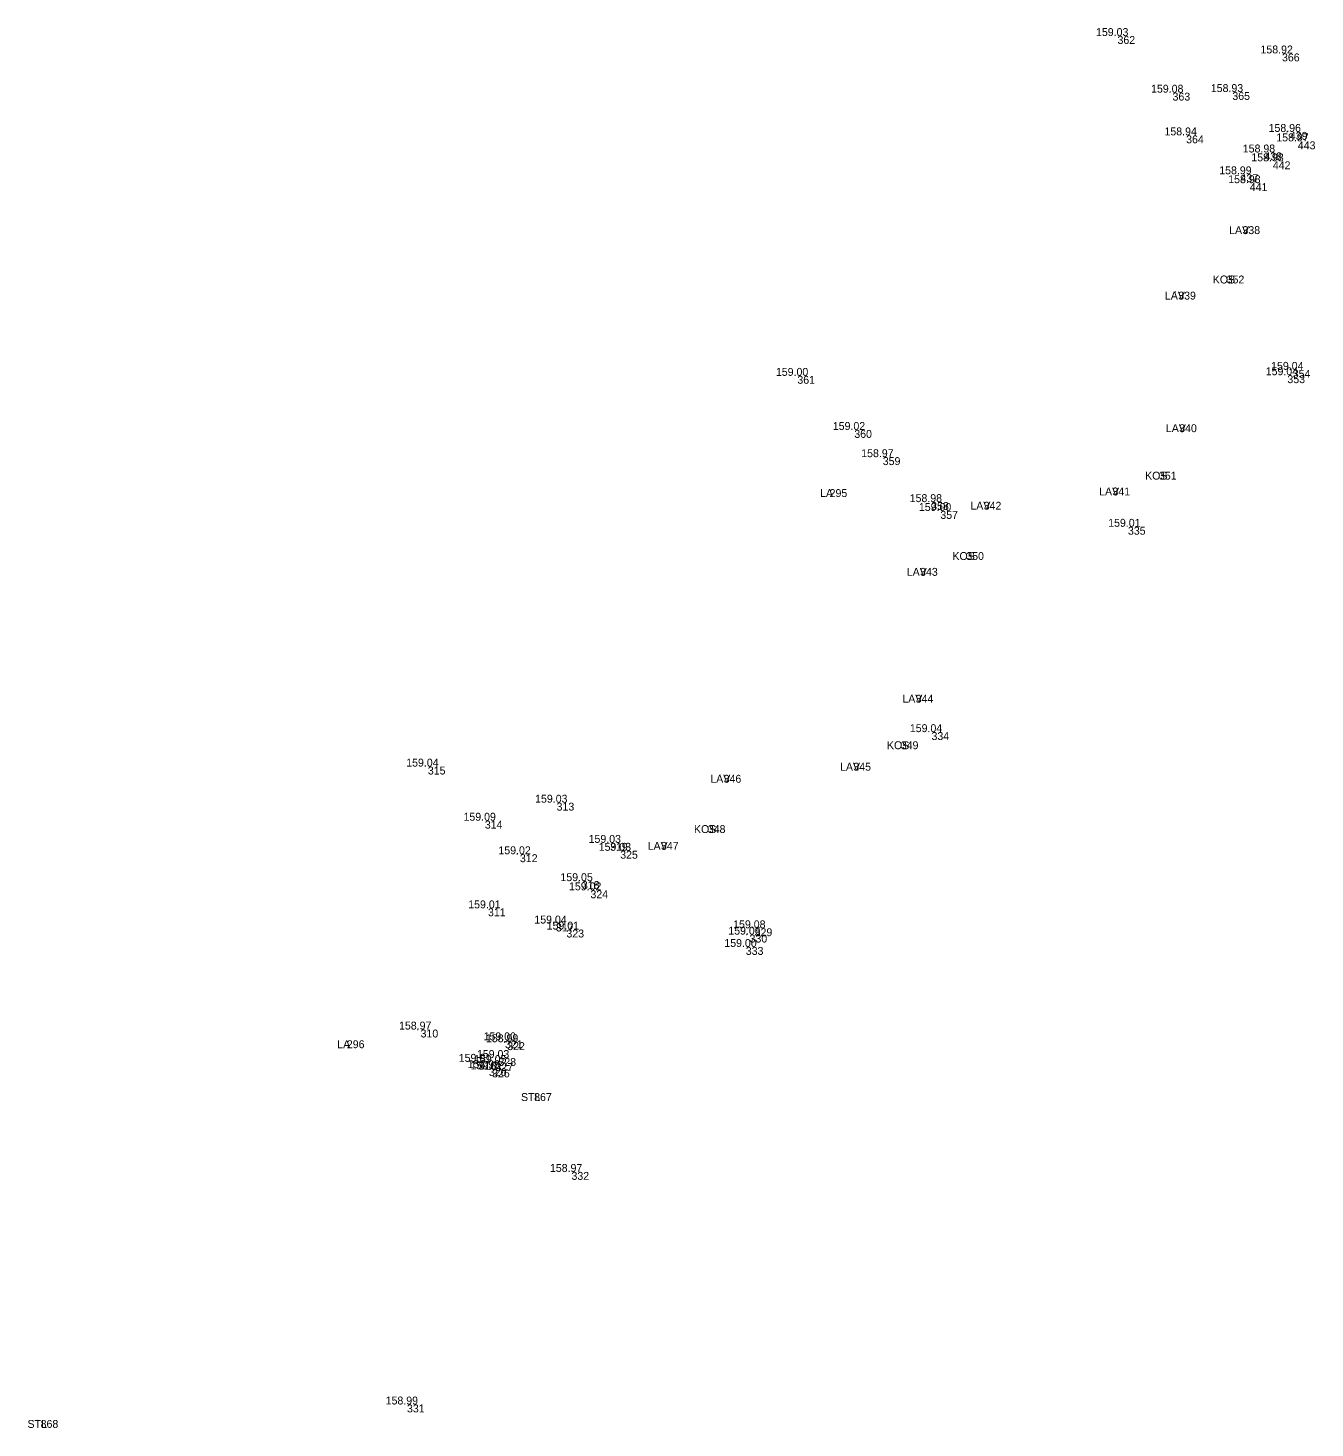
# Model space of a CAD drawing. Extents: x -583198 to -582878, y -1211024 to -1210637.
# Drawn here: x -583144.04 to -583103.35, y -1210950.28 to -1210906.04 of the extents above; entities that cross this region are included whole.
import ezdxf

# ---------------------------------------------------------------- set-up
doc = ezdxf.new("R2010")
doc.units = 0
for name, color, linetype in [('1   Kódy', 7, 'Continuous'), ('4   Body podrobné', 7, 'Continuous'), ('5   Body podrobné - čísla', 7, 'Continuous'), ('6   Body podrobné - výšky', 7, 'Continuous')]:
    doc.layers.add(name, color=color, linetype=linetype)

msp = doc.modelspace()

# ---------------------------------------------------------------- linework, layer by layer
at = {"layer": '4   Body podrobné'}
for p, q in [((-583109.69, -1210906.29), (-583109.689, -1210906.29)), ((-583104.49, -1210906.84), (-583104.489, -1210906.84)), ((-583107.95, -1210908.08), (-583107.949, -1210908.08)), ((-583106.06, -1210908.06), (-583106.059, -1210908.06)), ((-583104.24, -1210909.32), (-583104.239, -1210909.32)), ((-583107.52, -1210909.43), (-583107.519, -1210909.43)), ((-583103.99, -1210909.62), (-583103.989, -1210909.62)), ((-583105.05, -1210909.97), (-583105.049, -1210909.97)), ((-583104.78, -1210910.25), (-583104.779, -1210910.25)), ((-583105.8, -1210910.66), (-583105.799, -1210910.66)), ((-583105.51, -1210910.94), (-583105.509, -1210910.94)), ((-583105.74, -1210912.3), (-583105.739, -1210912.3)), ((-583106.24, -1210913.86), (-583106.239, -1210913.86)), ((-583107.77, -1210914.37), (-583107.769, -1210914.37)), ((-583104.15, -1210916.84), (-583104.149, -1210916.84)), ((-583119.81, -1210917.03), (-583119.809, -1210917.03)), ((-583104.32, -1210917.01), (-583104.319, -1210917.01)), ((-583107.74, -1210918.56), (-583107.739, -1210918.56)), ((-583118.01, -1210918.74), (-583118.009, -1210918.74)), ((-583117.11, -1210919.6), (-583117.109, -1210919.6)), ((-583108.38, -1210920.06), (-583108.379, -1210920.06)), ((-583118.79, -1210920.61), (-583118.789, -1210920.61)), ((-583109.85, -1210920.56), (-583109.849, -1210920.56)), ((-583115.58, -1210921.02), (-583115.579, -1210921.02)), ((-583115.29, -1210921.3), (-583115.289, -1210921.3)), ((-583113.92, -1210921.01), (-583113.919, -1210921.01)), ((-583109.36, -1210921.8), (-583109.359, -1210921.8)), ((-583114.47, -1210922.6), (-583114.469, -1210922.6)), ((-583115.93, -1210923.1), (-583115.929, -1210923.1)), ((-583116.07, -1210927.11), (-583116.069, -1210927.11)), ((-583115.57, -1210928.29), (-583115.569, -1210928.29)), ((-583116.54, -1210928.58), (-583116.539, -1210928.58)), ((-583118.04, -1210929.26), (-583118.039, -1210929.26)), ((-583131.49, -1210929.38), (-583131.489, -1210929.38)), ((-583122.14, -1210929.64), (-583122.139, -1210929.64)), ((-583127.42, -1210930.52), (-583127.419, -1210930.52)), ((-583129.69, -1210931.09), (-583129.689, -1210931.09)), ((-583122.64, -1210931.23), (-583122.639, -1210931.23)), ((-583125.73, -1210931.79), (-583125.729, -1210931.79)), ((-583124.12, -1210931.76), (-583124.119, -1210931.76)), ((-583128.58, -1210932.15), (-583128.579, -1210932.15)), ((-583125.41, -1210932.04), (-583125.409, -1210932.04)), ((-583126.62, -1210933), (-583126.619, -1210933)), ((-583126.35, -1210933.29), (-583126.349, -1210933.29)), ((-583129.59, -1210933.86), (-583129.589, -1210933.86)), ((-583127.44, -1210934.34), (-583127.439, -1210934.34)), ((-583127.11, -1210934.53), (-583127.109, -1210934.53)), ((-583121.16, -1210934.49), (-583121.159, -1210934.49)), ((-583121.32, -1210934.69), (-583121.319, -1210934.69)), ((-583121.44, -1210935.08), (-583121.439, -1210935.08)), ((-583131.72, -1210937.69), (-583131.719, -1210937.69)), ((-583134.05, -1210938.03), (-583134.049, -1210938.03)), ((-583129.05, -1210938.03), (-583129.049, -1210938.03)), ((-583128.98, -1210938.09), (-583128.979, -1210938.09)), ((-583129.26, -1210938.59), (-583129.259, -1210938.59)), ((-583129.89, -1210938.71), (-583129.889, -1210938.71)), ((-583129.56, -1210938.91), (-583129.559, -1210938.91)), ((-583129.46, -1210938.95), (-583129.459, -1210938.95)), ((-583129.35, -1210938.75), (-583129.349, -1210938.75)), ((-583128.13, -1210939.7), (-583128.129, -1210939.7)), ((-583126.95, -1210942.19), (-583126.949, -1210942.19)), ((-583132.15, -1210949.54), (-583132.149, -1210949.54)), ((-583143.73, -1210950.03), (-583143.729, -1210950.03))]:
    msp.add_line(p, q, dxfattribs=at)

# ---------------------------------------------------------------- texts
at = {"layer": '1   Kódy'}
for s, p in [('LAV', (-583106.068, -1210912.55)), ('KOS', (-583106.585, -1210914.11)), ('LAV', (-583108.098, -1210914.62)), ('LAV', (-583108.068, -1210918.81)), ('KOS', (-583108.725, -1210920.31)), ('LA', (-583119, -1210920.86)), ('LAV', (-583110.178, -1210920.81)), ('LAV', (-583114.248, -1210921.26)), ('KOS', (-583114.815, -1210922.85)), ('LAV', (-583116.258, -1210923.35)), ('LAV', (-583116.398, -1210927.36)), ('KOS', (-583116.885, -1210928.83)), ('LAV', (-583118.368, -1210929.51)), ('LAV', (-583122.468, -1210929.89)), ('KOS', (-583122.985, -1210931.48)), ('LAV', (-583124.448, -1210932.01)), ('LA', (-583134.26, -1210938.28)), ('STL', (-583128.452, -1210939.95)), ('STL', (-583144.052, -1210950.28))]:
    msp.add_text(s, height=0.25, dxfattribs=at).set_placement(p)
at = {"layer": '5   Body podrobné - čísla'}
for s, p in [(' 362', (-583109.69, -1210906.54)), (' 366', (-583104.49, -1210907.09)), (' 363', (-583107.95, -1210908.33)), (' 365', (-583106.06, -1210908.31)), (' 439', (-583104.24, -1210909.57)), (' 364', (-583107.52, -1210909.68)), (' 443', (-583103.99, -1210909.87)), (' 438', (-583105.05, -1210910.22)), (' 442', (-583104.78, -1210910.5)), (' 437', (-583105.8, -1210910.91)), (' 441', (-583105.51, -1210911.19)), (' 338', (-583105.74, -1210912.55)), (' 352', (-583106.24, -1210914.11)), (' 339', (-583107.77, -1210914.62)), (' 354', (-583104.15, -1210917.09)), (' 361', (-583119.81, -1210917.28)), (' 353', (-583104.32, -1210917.26)), (' 340', (-583107.74, -1210918.81)), (' 360', (-583118.01, -1210918.99)), (' 359', (-583117.11, -1210919.85)), (' 351', (-583108.38, -1210920.31)), (' 295', (-583118.79, -1210920.86)), (' 341', (-583109.85, -1210920.81)), (' 358', (-583115.58, -1210921.27)), (' 357', (-583115.29, -1210921.55)), (' 342', (-583113.92, -1210921.26)), (' 335', (-583109.36, -1210922.05)), (' 350', (-583114.47, -1210922.85)), (' 343', (-583115.93, -1210923.35)), (' 344', (-583116.07, -1210927.36)), (' 334', (-583115.57, -1210928.54)), (' 349', (-583116.54, -1210928.83)), (' 345', (-583118.04, -1210929.51)), (' 315', (-583131.49, -1210929.63)), (' 346', (-583122.14, -1210929.89)), (' 313', (-583127.42, -1210930.77)), (' 314', (-583129.69, -1210931.34)), (' 348', (-583122.64, -1210931.48)), (' 319', (-583125.73, -1210932.04)), (' 347', (-583124.12, -1210932.01)), (' 312', (-583128.58, -1210932.4)), (' 325', (-583125.41, -1210932.29)), (' 318', (-583126.62, -1210933.25)), (' 324', (-583126.35, -1210933.54)), (' 311', (-583129.59, -1210934.11)), (' 317', (-583127.44, -1210934.59)), (' 323', (-583127.11, -1210934.78)), (' 329', (-583121.16, -1210934.74)), (' 333', (-583121.44, -1210935.33)), (' 330', (-583121.32, -1210934.94)), (' 310', (-583131.72, -1210937.94)), (' 296', (-583134.05, -1210938.28)), (' 321', (-583129.05, -1210938.28)), (' 322', (-583128.98, -1210938.34)), (' 328', (-583129.26, -1210938.84)), (' 316', (-583129.89, -1210938.96)), (' 320', (-583129.56, -1210939.16)), (' 326', (-583129.46, -1210939.2)), (' 327', (-583129.35, -1210939)), (' 867', (-583128.13, -1210939.95)), (' 332', (-583126.95, -1210942.44)), (' 331', (-583132.15, -1210949.79)), (' 868', (-583143.73, -1210950.28))]:
    msp.add_text(s, height=0.25, dxfattribs=at).set_placement(p)
at = {"layer": '6   Body podrobné - výšky'}
for s, p in [('159.03', (-583110.276, -1210906.29)), ('158.92', (-583105.077, -1210906.84)), ('159.08', (-583108.536, -1210908.08)), ('158.93', (-583106.647, -1210908.06)), ('158.94', (-583108.112, -1210909.43)), ('158.96', (-583104.821, -1210909.32)), ('158.97', (-583104.578, -1210909.62)), ('158.98', (-583105.637, -1210909.97)), ('158.98', (-583105.367, -1210910.25)), ('158.99', (-583106.381, -1210910.66)), ('158.98', (-583106.097, -1210910.94)), ('159.00', (-583120.395, -1210917.03)), ('159.04', (-583104.911, -1210917.01)), ('159.04', (-583104.741, -1210916.84)), ('159.02', (-583118.596, -1210918.74)), ('158.97', (-583117.698, -1210919.6)), ('158.98', (-583116.167, -1210921.02)), ('159.00', (-583115.875, -1210921.3)), ('159.01', (-583109.891, -1210921.8)), ('159.04', (-583116.161, -1210928.29)), ('159.04', (-583132.081, -1210929.38)), ('159.03', (-583128.006, -1210930.52)), ('159.09', (-583130.27, -1210931.09)), ('159.03', (-583126.316, -1210931.79)), ('159.02', (-583129.166, -1210932.15)), ('159.03', (-583125.996, -1210932.04)), ('159.05', (-583127.206, -1210933)), ('159.02', (-583126.936, -1210933.29)), ('159.01', (-583130.121, -1210933.86)), ('159.04', (-583128.031, -1210934.34)), ('159.01', (-583127.641, -1210934.53)), ('159.06', (-583121.9, -1210934.69)), ('159.08', (-583121.746, -1210934.49)), ('159.00', (-583122.025, -1210935.08)), ('158.97', (-583132.308, -1210937.69)), ('159.00', (-583129.635, -1210938.03)), ('158.99', (-583129.561, -1210938.09)), ('159.01', (-583130.421, -1210938.71)), ('159.05', (-583129.936, -1210938.75)), ('159.03', (-583129.846, -1210938.59)), ('158.99', (-583130.141, -1210938.91)), ('159.07', (-583130.047, -1210938.95)), ('158.97', (-583127.538, -1210942.19)), ('158.99', (-583132.731, -1210949.54))]:
    msp.add_text(s, height=0.25, dxfattribs=at).set_placement(p)

doc.saveas('drawing.dxf')
